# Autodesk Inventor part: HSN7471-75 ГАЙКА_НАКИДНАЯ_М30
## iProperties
Created: 2011-02
Part Number: HSN7471-75 ГАЙКА_НАКИДНАЯ_М30
Document SubType Name: Modeling
Designer: Чернышев Юрий
Mass: 8.71904 g
Surface Area: 47.5982 cm^2
Volume: 8.71904 cm^3
Density: 1 g/cm^3
Author: Чернышев Юрий
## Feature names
1. ExtrusionBlind1
2. Hole1
3. Chamfer1
4. RevolutionAngle1
5. RevolutionAngle2
6. Hole2
